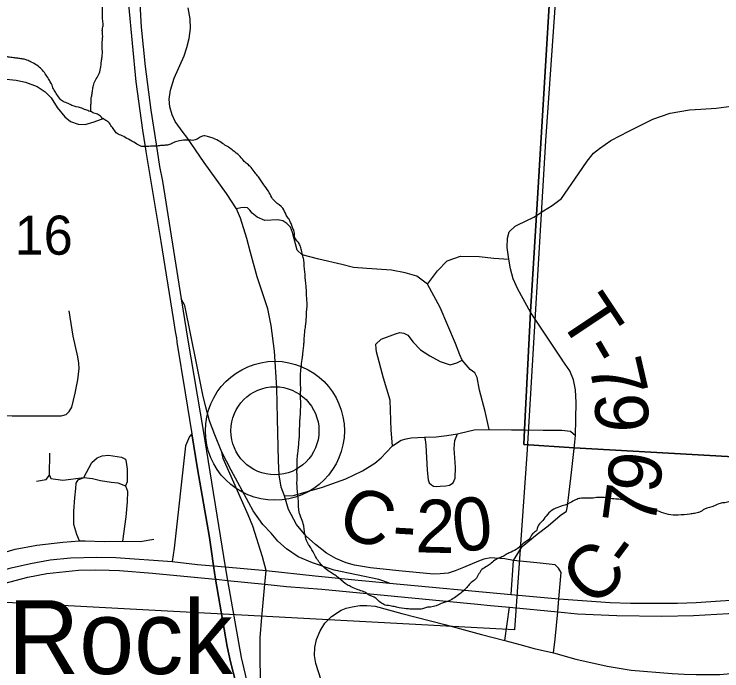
# Model space of a CAD drawing. Extents: x -20.2 to 34, y 0 to 22.
# Drawn here: x 5.177 to 5.935, y 15.933 to 16.636 of the extents above; entities that cross this region are included whole.
import ezdxf

# ---------------------------------------------------------------- set-up
doc = ezdxf.new("R2010")
doc.units = 0
for name, color, linetype in [('Default', 7, 'Continuous'), ('GM_X_County_Road', 7, 'Continuous'), ('GM_X_County_Road_Text', 7, 'Continuous'), ('GM_X_Interchange_Ramps', 7, 'Continuous'), ('GM_X_Minor_River', 7, 'Continuous'), ('GM_X_Section', 7, 'Continuous'), ('GM_X_Section_Text', 7, 'Continuous'), ('GM_X_State_Route', 7, 'Continuous'), ('GM_X_Township_Road', 7, 'Continuous'), ('GM_X_Township_Road_Text', 7, 'Continuous'), ('GM_X_Unincorporated', 7, 'Continuous'), ('GM_X_Unincorporated_Location', 7, 'Continuous'), ('GM_X_Unincorporated_Text', 7, 'Continuous'), ('GM_X_US_Route', 7, 'Continuous')]:
    doc.layers.add(name, color=color, linetype=linetype)

msp = doc.modelspace()

# ---------------------------------------------------------------- linework, layer by layer
at = {"layer": 'Default'}
for points in [[(6.33933, 16.13945), (5.77707, 16.17118), (5.72328, 16.17476), (5.72408, 16.19112), (5.73032, 16.31703), (5.73681, 16.42062), (5.78116, 17.15273)], [(5.78116, 17.15273), (5.73681, 16.42062), (5.73032, 16.31703), (5.72408, 16.19112), (5.72328, 16.17476), (5.77707, 16.17118), (6.33933, 16.13945)]]:
    msp.add_lwpolyline(points, dxfattribs=at)
at = {"layer": 'GM_X_County_Road'}
for p, q in [((5.68616, 16.19086), (5.70999, 16.1907)), ((5.77759, 16.17385), (5.77864, 16.18451)), ((5.70988, 16.01439), (5.71238, 16.0506))]:
    msp.add_line(p, q, dxfattribs=at)
for points in [[(5.35856, 16.50907), (5.34998, 16.52082), (5.34662, 16.52788), (5.34428, 16.53627), (5.3436, 16.5445), (5.34478, 16.55407), (5.34881, 16.567), (5.35955, 16.59118), (5.36224, 16.59991), (5.36476, 16.60948), (5.36627, 16.62023), (5.3661, 16.63064), (5.36375, 16.64223)], [(5.69207, 16.05318), (5.68777, 16.05346), (5.68054, 16.05218), (5.67458, 16.05006), (5.65884, 16.04325), (5.6499, 16.03963), (5.64224, 16.03729), (5.63352, 16.03644), (5.62671, 16.03622), (5.58947, 16.03963), (5.55905, 16.04303), (5.54203, 16.0458), (5.53288, 16.04835), (5.52203, 16.05282), (5.51203, 16.05857), (5.50001, 16.06779), (5.49022, 16.0767), (5.47983, 16.08917), (5.47121, 16.1052), (5.46679, 16.11992), (5.46321, 16.12925), (5.46112, 16.14231), (5.46064, 16.15744), (5.4593, 16.20261), (5.45879, 16.23569), (5.45611, 16.27499), (5.45275, 16.30236), (5.44922, 16.32016), (5.43767, 16.35457), (5.43058, 16.38061), (5.42656, 16.39538), (5.41984, 16.41705), (5.41555, 16.42719), (5.40489, 16.44358), (5.38105, 16.47666), (5.36224, 16.50403), (5.35856, 16.50907)], [(5.65507, 16.18716), (5.67004, 16.19052), (5.68616, 16.19086), (5.68179, 16.21017), (5.67591, 16.23317), (5.6734, 16.24661), (5.67088, 16.25181), (5.66567, 16.25534), (5.65711, 16.26508), (5.65459, 16.27095), (5.6502, 16.28306), (5.6336, 16.32167), (5.62016, 16.34669), (5.60875, 16.35509), (5.59615, 16.35861), (5.58155, 16.36164), (5.55501, 16.36331), (5.54074, 16.36449), (5.52848, 16.36751), (5.5038, 16.37339), (5.48583, 16.37792), (5.48062, 16.38279), (5.47542, 16.40176), (5.4734, 16.40747), (5.46938, 16.41151), (5.46518, 16.41419), (5.45997, 16.41553), (5.44586, 16.41486), (5.4378, 16.41839), (5.43226, 16.42259), (5.42991, 16.42595), (5.42723, 16.42813), (5.4237, 16.4288), (5.42018, 16.42818), (5.41555, 16.42719)], [(5.62016, 16.34669), (5.63075, 16.36096), (5.6412, 16.37137), (5.6553, 16.37644), (5.67555, 16.37611), (5.69106, 16.37428), (5.70722, 16.37342)], [(5.58255, 16.17339), (5.58104, 16.19019), (5.5802, 16.22226), (5.57315, 16.24577), (5.56559, 16.27415), (5.565, 16.27742), (5.56492, 16.28237), (5.57063, 16.28775), (5.58574, 16.29329), (5.59044, 16.29497), (5.59481, 16.29413), (5.59901, 16.29178), (5.60472, 16.28439), (5.61278, 16.27633), (5.62252, 16.26978), (5.6336, 16.26373), (5.64437, 16.26026), (5.65157, 16.26222), (5.65711, 16.26508)], [(5.70999, 16.1907), (5.72429, 16.1906), (5.74409, 16.19019), (5.76407, 16.19036), (5.77312, 16.18919), (5.77864, 16.18451)], [(5.46679, 16.11992), (5.47676, 16.12033), (5.50766, 16.1294), (5.53268, 16.1383), (5.55064, 16.14687), (5.56374, 16.15509), (5.57046, 16.16047), (5.576, 16.16634), (5.58255, 16.17339), (5.59179, 16.17944), (5.59733, 16.18112), (5.60254, 16.18196), (5.60959, 16.18246), (5.61698, 16.1828), (5.62943, 16.1832), (5.64082, 16.18464), (5.65207, 16.18649), (5.65507, 16.18716)], [(5.61698, 16.1828), (5.61744, 16.18017), (5.61835, 16.17408), (5.61976, 16.1473), (5.62074, 16.13697), (5.62203, 16.13402), (5.62423, 16.13166), (5.62657, 16.13032), (5.62962, 16.12992), (5.63377, 16.13026), (5.63964, 16.13057), (5.64351, 16.13124), (5.64753, 16.13377), (5.64989, 16.13897), (5.65006, 16.15056), (5.64939, 16.1608), (5.64872, 16.17054), (5.64922, 16.1791), (5.65207, 16.18649)], [(5.71238, 16.0506), (5.7216, 16.06559), (5.73756, 16.07878), (5.74926, 16.08772), (5.76202, 16.09878), (5.76894, 16.10371), (5.76995, 16.10891), (5.77432, 16.14501), (5.77728, 16.17065), (5.77759, 16.17385)], [(5.70309, 15.96495), (5.71884, 15.96091), (5.73437, 15.95644), (5.75523, 15.95181), (5.75692, 15.96666), (5.75952, 15.99571), (5.76077, 16.00973), (5.7633, 16.03793), (5.76054, 16.04239), (5.7567, 16.04623), (5.74093, 16.04796), (5.71238, 16.0506), (5.70282, 16.05247), (5.69207, 16.05318)], [(5.50607, 15.92261), (5.50054, 15.94048), (5.49922, 15.94888), (5.49947, 15.95771), (5.50118, 15.96623), (5.50501, 15.97559), (5.51011, 15.98346), (5.51713, 15.9907), (5.52756, 15.9975), (5.53309, 15.99963), (5.53947, 16.00112), (5.54777, 16.00261), (5.55501, 16.0024), (5.56415, 16.00197), (5.59267, 15.99388), (5.63884, 15.98218), (5.67777, 15.97155), (5.70309, 15.96495), (5.70798, 16.00059)], [(5.75523, 15.95181), (5.77883, 15.94516), (5.81245, 15.93751), (5.8382, 15.93346), (5.88202, 15.92985), (5.8949, 15.92921), (5.90776, 15.92857), (5.9333, 15.92857), (5.9567, 15.93091), (5.97393, 15.93495), (6.04638, 15.95554)]]:
    msp.add_lwpolyline(points, dxfattribs=at)
at = {"layer": 'GM_X_Interchange_Ramps'}
for points in [[(5.57956, 16.02628), (5.5679, 16.03041), (5.51999, 16.04021), (5.49692, 16.04814), (5.4816, 16.05473), (5.46926, 16.06304), (5.4599, 16.07154), (5.45254, 16.08006), (5.44379, 16.08925), (5.43349, 16.10381), (5.42879, 16.11255), (5.4099, 16.14731), (5.39988, 16.16671), (5.39231, 16.18528), (5.38673, 16.20008), (5.38278, 16.21471), (5.37933, 16.22803), (5.37308, 16.26009), (5.36026, 16.32388), (5.35628, 16.33081)], [(5.36777, 16.18617), (5.36535, 16.18345), (5.36082, 16.17347), (5.34879, 16.06401), (5.34661, 16.04948)], [(5.44575, 16.02546), (5.44735, 16.03987), (5.44328, 16.05459), (5.43309, 16.08746), (5.42815, 16.09963), (5.40119, 16.1598), (5.39988, 16.16671)], [(5.49038, 15.75812), (5.4828, 15.77801), (5.46179, 15.82446), (5.4509, 15.8641), (5.44535, 15.88847), (5.44363, 15.90567), (5.44133, 15.92417), (5.44076, 15.94714), (5.44092, 15.96778), (5.44274, 15.99016), (5.44484, 16.01367), (5.44575, 16.02546)]]:
    msp.add_lwpolyline(points, dxfattribs=at)
at = {"layer": 'GM_X_Minor_River'}
for points in [[(5.25977, 16.53108), (5.25946, 16.53684), (5.25987, 16.54102), (5.2599, 16.54519), (5.26069, 16.54936), (5.26149, 16.55391), (5.26228, 16.55921), (5.2646, 16.56489), (5.26768, 16.57056), (5.27001, 16.57737), (5.27083, 16.58533), (5.27163, 16.58988), (5.27175, 16.60582), (5.27219, 16.61379), (5.27184, 16.61796), (5.27264, 16.62327), (5.2723, 16.62897), (5.27196, 16.6339), (5.27203, 16.64339), (5.27171, 16.6506), (5.27174, 16.65478), (5.2714, 16.65971), (5.27105, 16.66389), (5.27148, 16.66996), (5.27154, 16.67831), (5.27313, 16.68741), (5.27356, 16.69386), (5.27398, 16.69916), (5.27403, 16.70638), (5.27445, 16.71168), (5.27373, 16.71625), (5.27461, 16.73218), (5.27465, 16.73749), (5.27393, 16.74243), (5.27435, 16.74774), (5.274, 16.75268), (5.27405, 16.75875), (5.27371, 16.76445), (5.27413, 16.76938), (5.27758, 16.77353), (5.28215, 16.77615), (5.28633, 16.7765), (5.29051, 16.7776), (5.29583, 16.77832), (5.30116, 16.78093), (5.30536, 16.78394), (5.30992, 16.78542), (5.31413, 16.78956), (5.31834, 16.79484), (5.32292, 16.79746), (5.32523, 16.80162), (5.33095, 16.80537), (5.33592, 16.81026), (5.34011, 16.81327), (5.34584, 16.81816), (5.34967, 16.8223), (5.35463, 16.8253), (5.35656, 16.8306), (5.35926, 16.83627), (5.36044, 16.84082), (5.36274, 16.84497), (5.36279, 16.85142), (5.36093, 16.85561), (5.35983, 16.86132), (5.36063, 16.86662), (5.36218, 16.87079), (5.3679, 16.87454), (5.37097, 16.87907), (5.37214, 16.88323), (5.37104, 16.88856), (5.36918, 16.89275), (5.36922, 16.89844), (5.36849, 16.90262), (5.36628, 16.91137), (5.36328, 16.91594), (5.35912, 16.9175), (5.35382, 16.91982), (5.34929, 16.92251), (5.34742, 16.9267), (5.3414, 16.93206), (5.33724, 16.93475), (5.33576, 16.93969), (5.33581, 16.94614), (5.33623, 16.95146), (5.33438, 16.95716), (5.33062, 16.96213), (5.32686, 16.96709), (5.32387, 16.97281), (5.32088, 16.9789), (5.31826, 16.98386), (5.31716, 16.9888), (5.31683, 16.99526), (5.31649, 17.00019), (5.31541, 17.00817), (5.3147, 17.01501), (5.31439, 17.02336), (5.31408, 17.03324)], [(5.21901, 16.55689), (5.21677, 16.56223), (5.21415, 16.56642), (5.21077, 16.57176), (5.20174, 16.58094), (5.19569, 16.5844), (5.19115, 16.58633), (5.18699, 16.58751), (5.18244, 16.5883), (5.17827, 16.58871), (5.17258, 16.58951), (5.16841, 16.59031), (5.16312, 16.593), (5.15896, 16.59418), (5.1548, 16.59611), (5.14798, 16.5973), (5.14343, 16.59847), (5.13356, 16.59779), (5.12859, 16.59289), (5.12666, 16.58873), (5.12511, 16.58381), (5.12391, 16.57547), (5.12349, 16.5713), (5.1227, 16.56675), (5.12152, 16.56183), (5.12035, 16.55766), (5.1188, 16.55312), (5.11535, 16.54821), (5.11, 16.54408), (5.10543, 16.54146), (5.1001, 16.53847), (5.09477, 16.53699), (5.08944, 16.53475), (5.08526, 16.53327), (5.08107, 16.53216), (5.07575, 16.53107), (5.06891, 16.52922), (5.06359, 16.5285), (5.05941, 16.5274), (5.05143, 16.52632), (5.04459, 16.52448), (5.03737, 16.52264), (5.03281, 16.52191), (5.0271, 16.52006), (5.02252, 16.51706), (5.01833, 16.51519), (5.01414, 16.51257), (5.00995, 16.51071), (5.0065, 16.50618), (5.0042, 16.50202), (5.00151, 16.49787), (4.99689, 16.48918), (4.99153, 16.48353), (4.98695, 16.48014), (4.98237, 16.47714), (4.9778, 16.4749), (4.97284, 16.47077), (4.95831, 16.45646), (4.9522, 16.45081), (4.94647, 16.4463), (4.94076, 16.44369), (4.93657, 16.44183), (4.93238, 16.44034), (4.92743, 16.43735), (4.9217, 16.43246), (4.90682, 16.4227), (4.90263, 16.4197), (4.89729, 16.41633), (4.89272, 16.41371), (4.88739, 16.41223), (4.88283, 16.4115), (4.87866, 16.41192), (4.87297, 16.41234), (4.86803, 16.41086), (4.86003, 16.40713), (4.85469, 16.403), (4.84782, 16.39736), (4.84132, 16.39133), (4.83635, 16.38682), (4.83177, 16.38268), (4.82605, 16.37931), (4.82147, 16.37555), (4.81575, 16.37256), (4.8108, 16.37032), (4.80584, 16.36656), (4.80315, 16.36203), (4.7978, 16.35714), (4.79435, 16.35299), (4.78976, 16.34809), (4.78593, 16.34281), (4.78095, 16.33754), (4.77713, 16.33301), (4.77443, 16.3281), (4.77401, 16.32317), (4.77246, 16.31862), (4.77015, 16.31447), (4.76632, 16.30918)], [(5.48027, 16.13475), (5.48068, 16.13968), (5.48034, 16.14461), (5.48037, 16.14879), (5.48041, 16.15334), (5.48085, 16.16169), (5.48126, 16.16586), (5.48207, 16.17268), (5.48251, 16.17951), (5.48292, 16.18406), (5.48296, 16.189), (5.48339, 16.19582), (5.48342, 16.2), (5.48384, 16.20455), (5.48429, 16.21479), (5.48435, 16.22162), (5.48402, 16.22884), (5.48444, 16.23415), (5.4841, 16.23946), (5.48414, 16.24478), (5.48419, 16.25085), (5.48501, 16.25919), (5.48622, 16.26829), (5.48664, 16.27284), (5.48744, 16.2789), (5.48786, 16.28421), (5.48829, 16.29066), (5.48871, 16.29559), (5.48951, 16.30166), (5.49035, 16.31152), (5.49078, 16.3191), (5.49121, 16.32517), (5.49087, 16.32973), (5.49055, 16.33808), (5.48986, 16.34681), (5.48914, 16.35289), (5.48881, 16.35896), (5.4881, 16.36504), (5.48777, 16.3715), (5.48667, 16.37644), (5.4852, 16.3829), (5.48372, 16.38785), (5.4811, 16.39204), (5.47809, 16.39624), (5.47738, 16.4027), (5.47552, 16.40727), (5.47403, 16.41145), (5.47179, 16.41602), (5.46879, 16.4206), (5.46505, 16.42784), (5.45714, 16.43473), (5.45338, 16.43932), (5.44964, 16.44618), (5.44475, 16.45305), (5.43913, 16.46144), (5.43536, 16.46564), (5.43123, 16.47137), (5.42294, 16.47902), (5.41843, 16.48437), (5.41202, 16.48935), (5.40711, 16.49319), (5.40183, 16.49627), (5.39616, 16.50011), (5.38936, 16.50319), (5.38443, 16.50475), (5.37913, 16.50517), (5.37455, 16.50255), (5.36999, 16.50069), (5.36353, 16.50074), (5.35442, 16.50005), (5.3491, 16.49857), (5.34377, 16.49596), (5.33921, 16.49523), (5.33427, 16.49489), (5.32933, 16.49417), (5.32516, 16.49421), (5.31833, 16.49388), (5.31302, 16.4943), (5.30735, 16.49738), (5.29979, 16.50161), (5.29299, 16.50546), (5.2877, 16.50778), (5.28431, 16.51198), (5.28093, 16.51656), (5.27755, 16.52076), (5.27339, 16.52307), (5.26887, 16.52728), (5.26433, 16.52921), (5.25866, 16.53154), (5.25412, 16.53309), (5.24844, 16.53541), (5.23935, 16.53776), (5.23406, 16.54046), (5.22877, 16.54278), (5.225, 16.54698), (5.22163, 16.55194), (5.21901, 16.55689)], [(6.03913, 16.12357), (6.0342, 16.12361), (6.02926, 16.12327), (6.02243, 16.1237), (6.01637, 16.12488), (6.00765, 16.12609), (6.0031, 16.12575), (5.99512, 16.12429), (5.99019, 16.12471), (5.98525, 16.12437), (5.98069, 16.12288), (5.97346, 16.12066), (5.9689, 16.11994), (5.96282, 16.11923), (5.95789, 16.11889), (5.94914, 16.1163), (5.94419, 16.11406), (5.93849, 16.11259), (5.93355, 16.11187), (5.92746, 16.10926), (5.9168, 16.10554), (5.91147, 16.10255), (5.90614, 16.10107), (5.90121, 16.10035), (5.88868, 16.09931), (5.88336, 16.09935), (5.87313, 16.10133), (5.86367, 16.10482), (5.85458, 16.10679), (5.84285, 16.11105), (5.83528, 16.11377), (5.82847, 16.11572), (5.82164, 16.11653), (5.81406, 16.11735), (5.80761, 16.11816), (5.80268, 16.1182), (5.79585, 16.11749), (5.79091, 16.11753), (5.78332, 16.11721), (5.77876, 16.11573), (5.77266, 16.11236), (5.76163, 16.10827), (5.75363, 16.10454), (5.74713, 16.09814), (5.74215, 16.0921), (5.73832, 16.0872), (5.73676, 16.08266), (5.73256, 16.07927), (5.72911, 16.07361), (5.72491, 16.07061), (5.71498, 16.06233), (5.70774, 16.05897), (5.70317, 16.05635), (5.6986, 16.05411), (5.69365, 16.05187), (5.68831, 16.04774), (5.68411, 16.04474), (5.67839, 16.04099), (5.67148, 16.03079), (5.6669, 16.02703), (5.65924, 16.01874), (5.65466, 16.01498), (5.64322, 16.00748), (5.63485, 16.00451), (5.62344, 16.0008), (5.61888, 16.00046), (5.6147, 15.99897), (5.60976, 15.99863), (5.60217, 15.99869), (5.59762, 15.99911), (5.58701, 16.00071), (5.58171, 16.00189), (5.57489, 16.00308), (5.5696, 16.00578), (5.56507, 16.00999), (5.556, 16.01461), (5.55185, 16.0173), (5.54579, 16.01925), (5.53898, 16.02233), (5.53407, 16.02465), (5.52577, 16.03155), (5.51633, 16.03807), (5.51067, 16.04229), (5.50578, 16.04688), (5.50202, 16.05185), (5.49865, 16.05794), (5.49378, 16.06633), (5.49041, 16.07205), (5.48931, 16.07699), (5.48821, 16.08231), (5.4875, 16.08801), (5.48268, 16.10285), (5.48197, 16.10931), (5.482, 16.11348), (5.48129, 16.11956), (5.48059, 16.12715), (5.48027, 16.13475)]]:
    msp.add_spline(points, degree=3, dxfattribs=at)
at = {"layer": 'GM_X_Section'}
msp.add_lwpolyline([(5.7813, 16.99904), (5.74634, 16.4999), (5.72677, 16.16939), (5.71316, 15.97646), (5.09557, 16.00955), (4.65934, 16.03232), (4.67151, 16.26512), (4.69409, 16.66092), (4.71521, 17.05295)], close=True, dxfattribs=at)
at = {"layer": 'GM_X_State_Route'}
for p, q in [((5.34419, 16.03533), (5.39302, 16.03069)), ((5.68772, 16.00251), (5.70798, 16.00059))]:
    msp.add_line(p, q, dxfattribs=at)
for points in [[(5.38875, 16.0602), (5.38675, 16.07539), (5.37372, 16.14882), (5.36777, 16.18617)], [(5.70798, 16.00059), (5.75952, 15.99571), (5.78079, 15.9937), (5.8229, 15.9917), (5.87097, 15.99099), (5.90512, 15.99177), (5.95501, 15.99474), (6.02628, 16.00299), (6.07084, 16.0112), (6.10003, 16.01721), (6.16012, 16.03272), (6.18755, 16.04048), (6.34217, 16.08621), (6.41816, 16.10902)], [(5.038, 15.98394), (5.04412, 15.987), (5.07786, 16.00388), (5.10087, 16.015), (5.1236, 16.02533), (5.13966, 16.03182), (5.15896, 16.03851), (5.17405, 16.04271), (5.19489, 16.04768), (5.21591, 16.0515), (5.23769, 16.05341), (5.26597, 16.05418), (5.28642, 16.0538), (5.34661, 16.04948), (5.3739, 16.04652), (5.39075, 16.045), (5.40354, 16.04385), (5.44735, 16.03987), (5.49968, 16.0343), (5.54593, 16.02972), (5.55767, 16.02852), (5.57956, 16.02628)], [(5.4332, 15.85923), (5.42891, 15.87114), (5.42133, 15.89552), (5.41467, 15.92013), (5.40903, 15.94217), (5.40544, 15.95858), (5.39319, 16.03068), (5.39075, 16.045), (5.38875, 16.0602)], [(5.06798, 15.98354), (5.11828, 16.00833), (5.14615, 16.02007), (5.16632, 16.02621), (5.19205, 16.03289), (5.21245, 16.03669), (5.24635, 16.04039), (5.26444, 16.04063), (5.27923, 16.04026), (5.29019, 16.03991), (5.32563, 16.03709), (5.34419, 16.03533)], [(5.39347, 16.03065), (5.39421, 16.03058), (5.40604, 16.02948), (5.44575, 16.02546)], [(5.44575, 16.02546), (5.46923, 16.02298), (5.50689, 16.01994), (5.67353, 16.00385), (5.68772, 16.00251)]]:
    msp.add_lwpolyline(points, dxfattribs=at)
at = {"layer": 'GM_X_Township_Road'}
for p, q in [((5.24078, 16.29104), (5.23628, 16.31785)), ((5.21541, 16.14207), (5.21574, 16.16555))]:
    msp.add_line(p, q, dxfattribs=at)
for points in [[(5.16574, 16.56652), (5.17971, 16.5649), (5.18963, 16.56267), (5.20198, 16.55802), (5.21068, 16.55255), (5.21696, 16.54588), (5.22364, 16.53555), (5.23153, 16.52584), (5.2378, 16.52077), (5.2461, 16.51774), (5.25359, 16.51734), (5.26311, 16.52037), (5.27383, 16.52442)], [(5.71702, 16.41014), (5.73414, 16.41819), (5.73702, 16.42009), (5.74447, 16.42501), (5.75363, 16.43065), (5.76374, 16.43816), (5.78183, 16.46471), (5.79099, 16.47811), (5.79781, 16.4868), (5.80437, 16.49196), (5.81637, 16.50019), (5.83587, 16.51053), (5.86147, 16.52321), (5.88003, 16.52955), (5.90081, 16.53315), (5.91293, 16.53379), (5.92937, 16.53496), (5.95607, 16.53869)], [(5.70722, 16.37342), (5.70547, 16.38578), (5.70571, 16.39564), (5.70759, 16.40245), (5.71416, 16.4088), (5.71702, 16.41014)], [(5.76513, 16.26446), (5.76391, 16.26626), (5.73053, 16.31651), (5.71689, 16.34115), (5.71202, 16.35223), (5.70899, 16.36298), (5.70722, 16.37342)], [(5.12441, 16.20282), (5.12809, 16.20536), (5.13297, 16.20705), (5.13784, 16.20686), (5.14187, 16.20693), (5.14689, 16.20656), (5.17533, 16.20556), (5.22784, 16.20555), (5.23328, 16.20705), (5.23647, 16.21023), (5.23909, 16.21473), (5.24284, 16.22992), (5.24565, 16.24417), (5.24716, 16.25631), (5.24659, 16.26198), (5.24565, 16.26873), (5.24078, 16.29104)], [(5.77864, 16.18451), (5.77935, 16.21974), (5.77868, 16.23334), (5.77633, 16.24426), (5.77247, 16.25366), (5.76513, 16.26446)], [(5.25218, 16.13944), (5.26068, 16.15563), (5.26634, 16.16049), (5.27161, 16.16292), (5.27848, 16.16333), (5.29245, 16.1615), (5.2967, 16.15928), (5.29751, 16.15584), (5.29852, 16.14835), (5.29833, 16.13499), (5.2965, 16.13054), (5.29873, 16.12487), (5.29844, 16.11367), (5.29709, 16.09757), (5.29347, 16.07143)], [(5.2013, 16.13562), (5.21186, 16.13761), (5.21541, 16.14207), (5.21675, 16.13863), (5.22971, 16.13661), (5.25218, 16.13944), (5.26148, 16.13863), (5.26983, 16.13646), (5.28145, 16.13467), (5.28841, 16.13377), (5.2965, 16.13054)], [(5.24752, 16.07184), (5.24468, 16.07851), (5.24125, 16.08944), (5.24144, 16.10362), (5.24246, 16.11798), (5.24347, 16.12791), (5.24368, 16.13357), (5.2461, 16.13722), (5.25218, 16.13944)], [(4.89473, 15.93319), (4.90221, 15.94149), (4.90707, 15.94594), (4.91314, 15.94918), (4.92164, 15.95202), (4.93277, 15.95525), (4.94472, 15.95748), (4.95788, 15.96254), (5.03115, 16.00018), (5.0945, 16.03115), (5.11636, 16.04189), (5.13923, 16.05079), (5.16271, 16.05807), (5.1785, 16.06273), (5.20178, 16.06698), (5.2295, 16.07022), (5.24752, 16.07184), (5.25359, 16.0717)], [(5.25359, 16.0717), (5.27383, 16.07123), (5.29347, 16.07143), (5.31229, 16.0712), (5.32704, 16.07344)]]:
    msp.add_lwpolyline(points, dxfattribs=at)
at = {"layer": 'GM_X_Unincorporated'}
for radius in [0.0744, 0.04716]:
    msp.add_circle((5.4567, 16.18958), radius, dxfattribs=at)
at = {"layer": 'GM_X_Unincorporated_Location'}
msp.add_line((5.4567, 16.18958), (5.4567, 16.18958), dxfattribs=at)
at = {"layer": 'GM_X_US_Route'}
for p, q in [((5.34419, 16.03533), (5.39302, 16.03069)), ((5.68772, 16.00251), (5.70798, 16.00059))]:
    msp.add_line(p, q, dxfattribs=at)
for points in [[(5.60372, 18.68667), (5.58837, 18.60774), (5.56682, 18.5139), (5.52237, 18.32928), (5.47402, 18.11981), (5.468, 18.09646), (5.44345, 17.99237), (5.4218, 17.90176), (5.39275, 17.78293), (5.35886, 17.63918), (5.32017, 17.47306), (5.30569, 17.40331), (5.29839, 17.35326), (5.29303, 17.29062), (5.29004, 17.23298), (5.29272, 17.13857), (5.29509, 17.08623), (5.29517, 17.08396), (5.30303, 16.86981), (5.30999, 16.68571), (5.31343, 16.62164), (5.31782, 16.57951), (5.32374, 16.53279), (5.32948, 16.4963)], [(5.29979, 16.64587), (5.30758, 16.56315), (5.31482, 16.51134), (5.31761, 16.49352), (5.31845, 16.4885)], [(5.32948, 16.4963), (5.33321, 16.47263), (5.33614, 16.45673), (5.35628, 16.33081), (5.36333, 16.28673), (5.38001, 16.19003), (5.40354, 16.04385), (5.40604, 16.02948), (5.42042, 15.94697), (5.42784, 15.91649), (5.44228, 15.86788), (5.44498, 15.86017)], [(5.31845, 16.4885), (5.3346, 16.39214), (5.34769, 16.3097), (5.34987, 16.29586), (5.35112, 16.2889), (5.35168, 16.28534), (5.35181, 16.28443), (5.36072, 16.23035), (5.36777, 16.18617)], [(5.36777, 16.18617), (5.37372, 16.14882), (5.38675, 16.07539), (5.38875, 16.0602)], [(5.57956, 16.02628), (5.70988, 16.01439), (5.76077, 16.00973), (5.81569, 16.00576), (5.83769, 16.00491), (5.86626, 16.00491), (5.88769, 16.00519), (5.90798, 16.00576), (5.93398, 16.00748), (5.94484, 16.00834), (5.95884, 16.00977), (5.97656, 16.01148), (6.00313, 16.01463), (6.03856, 16.01976), (6.0657, 16.02462), (6.0937, 16.03091), (6.1337, 16.04005), (6.41615, 16.12258)], [(5.70798, 16.00059), (5.75952, 15.99571), (5.78079, 15.9937), (5.8229, 15.9917), (5.87097, 15.99099), (5.90512, 15.99177), (5.95501, 15.99474), (6.02628, 16.00299), (6.07084, 16.0112), (6.10003, 16.01721), (6.16012, 16.03272), (6.18755, 16.04048), (6.34217, 16.08621), (6.41816, 16.10902)], [(5.38875, 16.0602), (5.39075, 16.045), (5.39319, 16.03068), (5.40544, 15.95858), (5.40903, 15.94217), (5.41467, 15.92013), (5.42133, 15.89552), (5.42891, 15.87114), (5.4332, 15.85923)], [(5.06798, 15.98354), (5.11828, 16.00833), (5.14615, 16.02007), (5.16632, 16.02621), (5.19205, 16.03289), (5.21245, 16.03669), (5.24635, 16.04039), (5.26444, 16.04063), (5.27923, 16.04026), (5.29019, 16.03991), (5.32563, 16.03709), (5.34419, 16.03533)], [(5.39347, 16.03065), (5.39421, 16.03058), (5.40604, 16.02948), (5.44575, 16.02546)], [(5.44575, 16.02546), (5.46923, 16.02298), (5.50689, 16.01994), (5.67353, 16.00385), (5.68772, 16.00251)]]:
    msp.add_lwpolyline(points, dxfattribs=at)

# ---------------------------------------------------------------- texts
at = {"layer": 'GM_X_County_Road_Text'}
for s, rotation, p in [('9', 83.31843, (5.86823, 16.12136)), ('7', 82.3826, (5.86351, 16.08593)), ('C', 340.95306, (5.52107, 16.07941)), ('2', 358.63524, (5.60671, 16.05957)), ('0', 6.79773, (5.65024, 16.05916)), ('-', 356.66124, (5.58148, 16.06101)), ('C', 43.6019, (5.79748, 15.9987)), ('-', 53.46101, (5.83809, 16.03864))]:
    msp.add_text(s, height=0.05682, rotation=rotation, dxfattribs=at).set_placement(p)
at = {"layer": 'GM_X_Section_Text'}
msp.add_text('16', height=0.041856, rotation=0.00001, dxfattribs=at).set_placement((5.17792, 16.37807))
at = {"layer": 'GM_X_Township_Road_Text'}
for s, rotation, p in [('T', 303.63052, (5.75926, 16.311)), ('-', 300.19041, (5.78228, 16.27644)), ('7', 283.00281, (5.79226, 16.26063)), ('9', 270.05174, (5.79968, 16.23016))]:
    msp.add_text(s, height=0.05682, rotation=rotation, dxfattribs=at).set_placement(p)
at = {"layer": 'GM_X_Unincorporated_Text'}
msp.add_text('Rock', height=0.078977, rotation=0.00001, dxfattribs=at).set_placement((5.17083, 15.92922))

doc.saveas('drawing.dxf')
